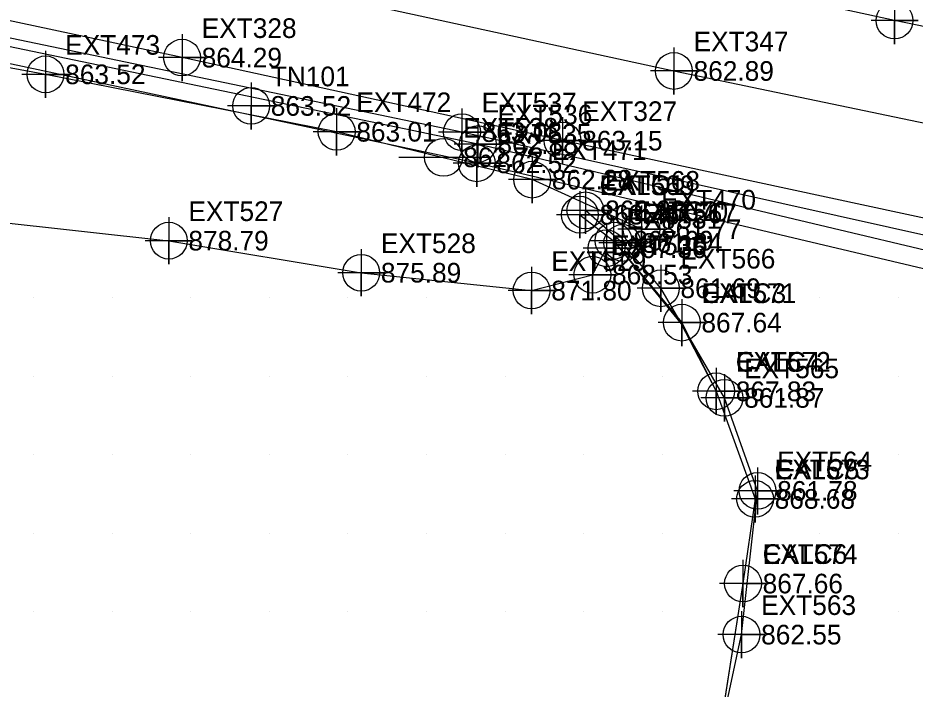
# Model space of a CAD drawing. Extents: x 1762120 to 1766775, y 709485 to 712965.
# Drawn here: x 1762528 to 1762642.2, y 712600.2 to 712685.6 of the extents above; entities that cross this region are included whole.
import ezdxf

# ---------------------------------------------------------------- set-up
doc = ezdxf.new("R2010")
doc.units = 0
for name, color, linetype in [('Default Symbol CELL', 7, 'Continuous'), ('Default Symbol Cogo Elevation', 7, 'Continuous'), ('Default Symbol Cogo Number', 7, 'Continuous'), ('Exist Building', 7, 'Continuous'), ('Exist Building Cogo Elevation', 7, 'Continuous'), ('Exist Building Cogo Number', 7, 'Continuous'), ('Exist Building Cogo Point CELL', 7, 'Continuous'), ('Exist DTM Breakline', 7, 'Continuous'), ('Exist DTM Breakline Cogo Elevation', 7, 'Continuous'), ('Exist DTM Breakline Cogo Number', 7, 'Continuous'), ('Exist DTM Breakline Cogo Point CELL', 7, 'Continuous'), ('Exist DTM Crownline', 7, 'Continuous'), ('Exist DTM Crownline Cogo Elevation', 7, 'Continuous'), ('Exist DTM Crownline Cogo Number', 7, 'Continuous'), ('Exist DTM Crownline Cogo Point CELL', 7, 'Continuous'), ('Exist DTM Drainline', 7, 'Continuous'), ('Exist DTM Drainline Cogo Elevation', 7, 'Continuous'), ('Exist DTM Drainline Cogo Number', 7, 'Continuous'), ('Exist DTM Drainline Cogo Point CELL', 7, 'Continuous'), ('Exist DTM QL2 LIDAR Elevation Point', 7, 'Continuous'), ('Exist Roads EOP', 7, 'Continuous'), ('Exist Roads EOP Cogo Elevation', 7, 'Continuous'), ('Exist Roads EOP Cogo Number', 7, 'Continuous'), ('Exist Roads EOP Cogo Point CELL', 7, 'Continuous'), ('Exist Utilities Telephone Pole CELL', 7, 'Continuous'), ('Exist Utilities Telephone Pole Cogo Elevation', 7, 'Continuous'), ('Exist Utilities Telephone Pole Cogo Number', 7, 'Continuous'), ('Exist Utilities Telephone UG FO SUE LOS C', 7, 'Continuous'), ('Exist Utilities Telephone UG FO SUE LOS C Cogo Elevation', 7, 'Continuous'), ('Exist Utilities Telephone UG FO SUE LOS C Cogo Number', 7, 'Continuous'), ('Exist Utilities Telephone UG FO SUE LOS C Cogo Point CELL', 7, 'Continuous'), ('Exist Utilities Water UG Line SUE LOS C', 7, 'Continuous'), ('Exist Utilities Water UG Line SUE LOS C Cogo Elevation', 7, 'Continuous'), ('Exist Utilities Water UG Line SUE LOS C Cogo Number', 7, 'Continuous'), ('Exist Utilities Water UG Line SUE LOS C Cogo Point CELL', 7, 'Continuous')]:
    doc.layers.add(name, color=color, linetype=linetype)

msp = doc.modelspace()

# ---------------------------------------------------------------- linework, layer by layer
at = {"layer": 'Default Symbol CELL'}
msp.add_lwpolyline([(1762557.68, 712677.39), (1762557.68, 712671.39), (1762557.68, 712674.39), (1762560.68, 712674.39), (1762554.68, 712674.39)], dxfattribs=at)
msp.add_circle((1762557.68, 712674.39), 2.34, dxfattribs=at)
at = {"layer": 'Exist Building'}
msp.add_lwpolyline([(1762599.52, 712660.55), (1762603.8, 712657.24), (1762612.48, 712646.81), (1762616.85, 712638.07), (1762621.8, 712624.37), (1762620.27, 712613.6), (1762616.96, 712592.54)], dxfattribs=at)
at = {"layer": 'Exist Building Cogo Point CELL'}
for points in [[(1762599.52, 712663.55), (1762599.52, 712657.55), (1762599.52, 712660.55), (1762602.52, 712660.55), (1762596.52, 712660.55)], [(1762603.8, 712660.24), (1762603.8, 712654.24), (1762603.8, 712657.24), (1762606.8, 712657.24), (1762600.8, 712657.24)], [(1762612.48, 712649.81), (1762612.48, 712643.81), (1762612.48, 712646.81), (1762615.48, 712646.81), (1762609.48, 712646.81)], [(1762616.85, 712641.07), (1762616.85, 712635.07), (1762616.85, 712638.07), (1762619.85, 712638.07), (1762613.85, 712638.07)], [(1762621.8, 712627.37), (1762621.8, 712621.37), (1762621.8, 712624.37), (1762624.8, 712624.37), (1762618.8, 712624.37)], [(1762620.27, 712616.6), (1762620.27, 712610.6), (1762620.27, 712613.6), (1762623.27, 712613.6), (1762617.27, 712613.6)]]:
    msp.add_lwpolyline(points, dxfattribs=at)
for centre in [(1762599.52, 712660.55), (1762603.8, 712657.24), (1762612.48, 712646.81), (1762616.85, 712638.07), (1762621.8, 712624.37), (1762620.27, 712613.6)]:
    msp.add_circle(centre, 2.34, dxfattribs=at)
at = {"layer": 'Exist DTM Breakline'}
for points in [[(1762183.31, 712740.13), (1762222.89, 712732.5), (1762242.72, 712728.2), (1762260.87, 712722.96), (1762294.89, 712713.63), (1762324.74, 712704.89), (1762362.52, 712694.51), (1762387.62, 712687.36), (1762406.26, 712681.83), (1762438.55, 712677.19), (1762458.9, 712672.51), (1762474.39, 712669.93), (1762496.2, 712663.55), (1762513.05, 712661.01), (1762547.19, 712657.24), (1762571.69, 712653.16), (1762593.37, 712650.89), (1762601.1, 712652.91), (1762602.91, 712656.27)], [(1762599.52, 712660.55), (1762603.8, 712657.24), (1762612.39, 712646.67), (1762616.85, 712638.07), (1762621.8, 712624.37), (1762620.27, 712613.6), (1762616.98, 712592.72)], [(1762615.11, 712583.99), (1762620.08, 712607.1), (1762622.12, 712625.39), (1762617.91, 712637.23), (1762609.81, 712651.18), (1762604.91, 712656.95), (1762600.21, 712661.1)]]:
    msp.add_lwpolyline(points, dxfattribs=at)
at = {"layer": 'Exist DTM Breakline Cogo Point CELL'}
for points in [[(1762600.21, 712664.1), (1762600.21, 712658.1), (1762600.21, 712661.1), (1762603.21, 712661.1), (1762597.21, 712661.1)], [(1762599.52, 712663.55), (1762599.52, 712657.55), (1762599.52, 712660.55), (1762602.52, 712660.55), (1762596.52, 712660.55)], [(1762547.19, 712660.24), (1762547.19, 712654.24), (1762547.19, 712657.24), (1762550.19, 712657.24), (1762544.19, 712657.24)], [(1762603.8, 712660.24), (1762603.8, 712654.24), (1762603.8, 712657.24), (1762606.8, 712657.24), (1762600.8, 712657.24)], [(1762602.91, 712659.27), (1762602.91, 712653.27), (1762602.91, 712656.27), (1762605.91, 712656.27), (1762599.91, 712656.27)], [(1762604.91, 712659.95), (1762604.91, 712653.95), (1762604.91, 712656.95), (1762607.91, 712656.95), (1762601.91, 712656.95)], [(1762571.69, 712656.16), (1762571.69, 712650.16), (1762571.69, 712653.16), (1762574.69, 712653.16), (1762568.69, 712653.16)], [(1762601.1, 712655.91), (1762601.1, 712649.91), (1762601.1, 712652.91), (1762604.1, 712652.91), (1762598.1, 712652.91)], [(1762593.37, 712653.89), (1762593.37, 712647.89), (1762593.37, 712650.89), (1762596.37, 712650.89), (1762590.37, 712650.89)], [(1762609.81, 712654.18), (1762609.81, 712648.18), (1762609.81, 712651.18), (1762612.81, 712651.18), (1762606.81, 712651.18)], [(1762612.48, 712649.81), (1762612.48, 712643.81), (1762612.48, 712646.81), (1762615.48, 712646.81), (1762609.48, 712646.81)], [(1762616.85, 712641.07), (1762616.85, 712635.07), (1762616.85, 712638.07), (1762619.85, 712638.07), (1762613.85, 712638.07)], [(1762617.91, 712640.23), (1762617.91, 712634.23), (1762617.91, 712637.23), (1762620.91, 712637.23), (1762614.91, 712637.23)], [(1762622.12, 712628.39), (1762622.12, 712622.39), (1762622.12, 712625.39), (1762625.12, 712625.39), (1762619.12, 712625.39)], [(1762621.8, 712627.37), (1762621.8, 712621.37), (1762621.8, 712624.37), (1762624.8, 712624.37), (1762618.8, 712624.37)], [(1762620.27, 712616.6), (1762620.27, 712610.6), (1762620.27, 712613.6), (1762623.27, 712613.6), (1762617.27, 712613.6)], [(1762620.08, 712610.1), (1762620.08, 712604.1), (1762620.08, 712607.1), (1762623.08, 712607.1), (1762617.08, 712607.1)]]:
    msp.add_lwpolyline(points, dxfattribs=at)
for centre in [(1762599.52, 712660.55), (1762600.21, 712661.1), (1762547.19, 712657.24), (1762603.8, 712657.24), (1762604.91, 712656.95), (1762602.91, 712656.27), (1762571.69, 712653.16), (1762601.1, 712652.91), (1762609.81, 712651.18), (1762593.37, 712650.89), (1762612.48, 712646.81), (1762616.85, 712638.07), (1762617.91, 712637.23), (1762622.12, 712625.39), (1762621.8, 712624.37), (1762620.27, 712613.6), (1762620.08, 712607.1)]:
    msp.add_circle(centre, 2.34, dxfattribs=at)
at = {"layer": 'Exist DTM Crownline'}
msp.add_lwpolyline([(1762166.55, 712774.69), (1762217.29, 712763.93), (1762266.93, 712753.16), (1762315.99, 712742.65), (1762361.3, 712733.13), (1762409.52, 712722.71), (1762461.51, 712711.51), (1762512.12, 712700.31), (1762561, 712689.86), (1762611.48, 712678.84), (1762663.77, 712667.96), (1762715.27, 712656.97), (1762767.73, 712645.75), (1762820.16, 712634.42), (1762873.56, 712623.12), (1762907.32, 712615.87), (1762954.84, 712607.61), (1762970.66, 712604.72)], dxfattribs=at)
at = {"layer": 'Exist DTM Crownline Cogo Point CELL'}
msp.add_lwpolyline([(1762611.48, 712681.84), (1762611.48, 712675.84), (1762611.48, 712678.84), (1762614.48, 712678.84), (1762608.48, 712678.84)], dxfattribs=at)
msp.add_circle((1762611.48, 712678.84), 2.34, dxfattribs=at)
at = {"layer": 'Exist DTM Drainline'}
msp.add_lwpolyline([(1762607.34, 712658.7), (1762593.44, 712665.01), (1762568.56, 712671.1), (1762531.51, 712678.41), (1762506.12, 712683.06), (1762483.93, 712688.33), (1762453.21, 712695.91), (1762419.5, 712702.24), (1762383.47, 712709.67), (1762355.69, 712715.12), (1762331.82, 712720.47), (1762302.4, 712727.8), (1762276.98, 712733.51), (1762241.78, 712739.93), (1762203.56, 712744.94), (1762183.53, 712748.07)], dxfattribs=at)
at = {"layer": 'Exist DTM Drainline Cogo Point CELL'}
for points in [[(1762531.51, 712681.41), (1762531.51, 712675.41), (1762531.51, 712678.41), (1762534.51, 712678.41), (1762528.51, 712678.41)], [(1762568.56, 712674.1), (1762568.56, 712668.1), (1762568.56, 712671.1), (1762571.56, 712671.1), (1762565.56, 712671.1)], [(1762593.44, 712668.01), (1762593.44, 712662.01), (1762593.44, 712665.01), (1762596.44, 712665.01), (1762590.44, 712665.01)], [(1762607.34, 712661.7), (1762607.34, 712655.7), (1762607.34, 712658.7), (1762610.34, 712658.7), (1762604.34, 712658.7)]]:
    msp.add_lwpolyline(points, dxfattribs=at)
for centre in [(1762531.51, 712678.41), (1762568.56, 712671.1), (1762593.44, 712665.01), (1762607.34, 712658.7)]:
    msp.add_circle(centre, 2.34, dxfattribs=at)
at = {"layer": 'Exist DTM QL2 LIDAR Elevation Point'}
for p, q in [((1762620, 712660), (1762620, 712660)), ((1762530, 712650), (1762530, 712650)), ((1762540, 712650), (1762540, 712650)), ((1762550, 712650), (1762550, 712650)), ((1762560, 712650), (1762560, 712650)), ((1762570, 712650), (1762570, 712650)), ((1762580, 712650), (1762580, 712650)), ((1762620, 712650), (1762620, 712650)), ((1762630, 712650), (1762630, 712650)), ((1762640, 712650), (1762640, 712650)), ((1762530, 712640), (1762530, 712640)), ((1762540, 712640), (1762540, 712640)), ((1762550, 712640), (1762550, 712640)), ((1762560, 712640), (1762560, 712640)), ((1762570, 712640), (1762570, 712640)), ((1762580, 712640), (1762580, 712640)), ((1762590, 712640), (1762590, 712640)), ((1762600, 712640), (1762600, 712640)), ((1762610, 712640), (1762610, 712640)), ((1762620, 712640), (1762620, 712640)), ((1762630, 712640), (1762630, 712640)), ((1762640, 712640), (1762640, 712640)), ((1762530, 712630), (1762530, 712630)), ((1762540, 712630), (1762540, 712630)), ((1762550, 712630), (1762550, 712630)), ((1762560, 712630), (1762560, 712630)), ((1762570, 712630), (1762570, 712630)), ((1762580, 712630), (1762580, 712630)), ((1762590, 712630), (1762590, 712630)), ((1762600, 712630), (1762600, 712630)), ((1762610, 712630), (1762610, 712630)), ((1762630, 712630), (1762630, 712630)), ((1762640, 712630), (1762640, 712630)), ((1762530, 712620), (1762530, 712620)), ((1762540, 712620), (1762540, 712620)), ((1762550, 712620), (1762550, 712620)), ((1762560, 712620), (1762560, 712620)), ((1762570, 712620), (1762570, 712620)), ((1762580, 712620), (1762580, 712620)), ((1762590, 712620), (1762590, 712620)), ((1762600, 712620), (1762600, 712620)), ((1762610, 712620), (1762610, 712620)), ((1762630, 712620), (1762630, 712620)), ((1762640, 712620), (1762640, 712620)), ((1762530, 712610), (1762530, 712610)), ((1762540, 712610), (1762540, 712610)), ((1762550, 712610), (1762550, 712610)), ((1762560, 712610), (1762560, 712610)), ((1762570, 712610), (1762570, 712610)), ((1762580, 712610), (1762580, 712610)), ((1762590, 712610), (1762590, 712610)), ((1762600, 712610), (1762600, 712610)), ((1762610, 712610), (1762610, 712610)), ((1762630, 712610), (1762630, 712610)), ((1762640, 712610), (1762640, 712610))]:
    msp.add_line(p, q, dxfattribs=at)
at = {"layer": 'Exist Roads EOP'}
for points in [[(1762972.64, 712616.33), (1762930.48, 712622.91), (1762881.99, 712633.2), (1762831.97, 712644.06), (1762782.82, 712654.41), (1762735.74, 712664.41), (1762686.68, 712675.53), (1762639.56, 712685.26), (1762589.4, 712696.15), (1762546.23, 712705.49), (1762496.4, 712716.08), (1762446.15, 712726.9), (1762396.23, 712737.69), (1762346.43, 712748.23), (1762295.97, 712759.18), (1762245.1, 712770.1), (1762193.68, 712780.97), (1762169, 712786.42)], [(1762974.58, 712585.31), (1762927.98, 712597.84), (1762890.67, 712606.3), (1762842.51, 712617.09), (1762793.23, 712628.15), (1762744.7, 712638.79), (1762696.33, 712649.07), (1762645.67, 712659.58), (1762597.31, 712669.97), (1762548.88, 712680.54), (1762499.87, 712691.04), (1762451.78, 712701.31), (1762402.08, 712712.16), (1762353.64, 712722.59), (1762304.8, 712733.11), (1762255.13, 712743.65), (1762207.34, 712753.91), (1762164.28, 712763.06), (1762150.69, 712765.78)]]:
    msp.add_lwpolyline(points, dxfattribs=at)
at = {"layer": 'Exist Roads EOP Cogo Point CELL'}
for points in [[(1762639.56, 712688.26), (1762639.56, 712682.26), (1762639.56, 712685.26), (1762642.56, 712685.26), (1762636.56, 712685.26)], [(1762548.88, 712683.54), (1762548.88, 712677.54), (1762548.88, 712680.54), (1762551.88, 712680.54), (1762545.88, 712680.54)], [(1762597.31, 712672.97), (1762597.31, 712666.97), (1762597.31, 712669.97), (1762600.31, 712669.97), (1762594.31, 712669.97)]]:
    msp.add_lwpolyline(points, dxfattribs=at)
for centre in [(1762639.56, 712685.26), (1762548.88, 712680.54), (1762597.31, 712669.97)]:
    msp.add_circle(centre, 2.34, dxfattribs=at)
at = {"layer": 'Exist Utilities Telephone Pole CELL'}
for p, q in [((1762576.49, 712667.85), (1762587.82, 712667.85)), ((1762582.16, 712667.85), (1762582.16, 712667.85))]:
    msp.add_line(p, q, dxfattribs=at)
msp.add_circle((1762582.16, 712667.85), 2.41, dxfattribs=at)
at = {"layer": 'Exist Utilities Telephone UG FO SUE LOS C'}
for points in [[(1762655.15, 712653.25), (1762586.52, 712669.54), (1762459.67, 712695.94), (1762295.49, 712731.66), (1762171.26, 712757.55)], [(1762655.08, 712650.85), (1762586.39, 712667.09), (1762459.96, 712694.03), (1762295.89, 712729.25), (1762171.95, 712754.92)]]:
    msp.add_lwpolyline(points, dxfattribs=at)
at = {"layer": 'Exist Utilities Telephone UG FO SUE LOS C Cogo Point CELL'}
for points in [[(1762586.52, 712672.54), (1762586.52, 712666.54), (1762586.52, 712669.54), (1762589.52, 712669.54), (1762583.52, 712669.54)], [(1762586.39, 712670.09), (1762586.39, 712664.09), (1762586.39, 712667.09), (1762589.39, 712667.09), (1762583.39, 712667.09)]]:
    msp.add_lwpolyline(points, dxfattribs=at)
for centre in [(1762586.52, 712669.54), (1762586.39, 712667.09)]:
    msp.add_circle(centre, 2.34, dxfattribs=at)
at = {"layer": 'Exist Utilities Water UG Line SUE LOS C'}
msp.add_lwpolyline([(1762652.6, 712655.88), (1762584.51, 712671.06), (1762460.33, 712696.95), (1762295.33, 712732.74), (1762171.02, 712758.92)], dxfattribs=at)
at = {"layer": 'Exist Utilities Water UG Line SUE LOS C Cogo Point CELL'}
msp.add_lwpolyline([(1762584.51, 712674.06), (1762584.51, 712668.06), (1762584.51, 712671.06), (1762587.51, 712671.06), (1762581.51, 712671.06)], dxfattribs=at)
msp.add_circle((1762584.51, 712671.06), 2.34, dxfattribs=at)

# ---------------------------------------------------------------- texts
at = {"layer": 'Default Symbol Cogo Elevation'}
msp.add_text('863.52', height=2.5, dxfattribs=at).set_placement((1762560.18, 712673.14))
at = {"layer": 'Default Symbol Cogo Number'}
msp.add_text('TN101', height=2.5, dxfattribs=at).set_placement((1762560.18, 712676.89))
at = {"layer": 'Exist Building Cogo Elevation'}
for s, p in [('863.45', (1762602.02, 712659.3)), ('867.69', (1762606.3, 712655.99)), ('867.64', (1762614.98, 712645.56)), ('867.83', (1762619.35, 712636.82)), ('868.68', (1762624.3, 712623.12)), ('867.66', (1762622.77, 712612.35))]:
    msp.add_text(s, height=2.5, dxfattribs=at).set_placement(p)
at = {"layer": 'Exist Building Cogo Number'}
for s, p in [('CALC1', (1762602.02, 712663.05)), ('CALC2', (1762606.3, 712659.74)), ('CALC3', (1762614.98, 712649.31)), ('CALC4', (1762619.35, 712640.57)), ('CALC5', (1762624.3, 712626.87)), ('CALC6', (1762622.77, 712616.1))]:
    msp.add_text(s, height=2.5, dxfattribs=at).set_placement(p)
at = {"layer": 'Exist DTM Breakline Cogo Elevation'}
for s, p in [('863.45', (1762602.02, 712659.3)), ('862.28', (1762602.71, 712659.85)), ('878.79', (1762549.69, 712655.99)), ('867.69', (1762606.3, 712655.99)), ('861.84', (1762607.41, 712655.7)), ('867.36', (1762605.41, 712655.02)), ('875.89', (1762574.19, 712651.91)), ('868.53', (1762603.6, 712651.67)), ('871.80', (1762595.87, 712649.64)), ('861.69', (1762612.31, 712649.94)), ('867.64', (1762614.98, 712645.56)), ('867.83', (1762619.35, 712636.82)), ('861.87', (1762620.41, 712635.98)), ('861.78', (1762624.62, 712624.14)), ('868.68', (1762624.3, 712623.12)), ('867.66', (1762622.77, 712612.35)), ('862.55', (1762622.58, 712605.85))]:
    msp.add_text(s, height=2.5, dxfattribs=at).set_placement(p)
at = {"layer": 'Exist DTM Breakline Cogo Number'}
for s, p in [('EXT568', (1762602.71, 712663.6)), ('EXT569', (1762602.02, 712663.05)), ('EXT527', (1762549.69, 712659.74)), ('EXT531', (1762605.41, 712658.77)), ('EXT570', (1762606.3, 712659.74)), ('EXT567', (1762607.41, 712659.45)), ('EXT528', (1762574.19, 712655.66)), ('EXT530', (1762603.6, 712655.42)), ('EXT529', (1762595.87, 712653.39)), ('EXT566', (1762612.31, 712653.69)), ('EXT571', (1762614.98, 712649.31)), ('EXT572', (1762619.35, 712640.57)), ('EXT565', (1762620.41, 712639.73)), ('EXT573', (1762624.3, 712626.87)), ('EXT564', (1762624.62, 712627.89)), ('EXT574', (1762622.77, 712616.1)), ('EXT563', (1762622.58, 712609.6))]:
    msp.add_text(s, height=2.5, dxfattribs=at).set_placement(p)
at = {"layer": 'Exist DTM Crownline Cogo Elevation'}
msp.add_text('862.89', height=2.5, dxfattribs=at).set_placement((1762613.98, 712677.59))
at = {"layer": 'Exist DTM Crownline Cogo Number'}
msp.add_text('EXT347', height=2.5, dxfattribs=at).set_placement((1762613.98, 712681.34))
at = {"layer": 'Exist DTM Drainline Cogo Elevation'}
for s, p in [('863.52', (1762534.01, 712677.16)), ('863.01', (1762571.06, 712669.85)), ('862.28', (1762595.94, 712663.76)), ('861.77', (1762609.84, 712657.45))]:
    msp.add_text(s, height=2.5, dxfattribs=at).set_placement(p)
at = {"layer": 'Exist DTM Drainline Cogo Number'}
for s, p in [('EXT473', (1762534.01, 712680.91)), ('EXT472', (1762571.06, 712673.6)), ('EXT471', (1762595.94, 712667.51)), ('EXT470', (1762609.84, 712661.2))]:
    msp.add_text(s, height=2.5, dxfattribs=at).set_placement(p)
at = {"layer": 'Exist Roads EOP Cogo Elevation'}
for s, p in [('864.29', (1762551.38, 712679.29)), ('863.15', (1762599.81, 712668.72))]:
    msp.add_text(s, height=2.5, dxfattribs=at).set_placement(p)
at = {"layer": 'Exist Roads EOP Cogo Number'}
for s, p in [('EXT328', (1762551.38, 712683.04)), ('EXT327', (1762599.81, 712672.47))]:
    msp.add_text(s, height=2.5, dxfattribs=at).set_placement(p)
at = {"layer": 'Exist Utilities Telephone Pole Cogo Elevation'}
msp.add_text('862.72', height=2.5, dxfattribs=at).set_placement((1762584.66, 712666.6))
at = {"layer": 'Exist Utilities Telephone Pole Cogo Number'}
msp.add_text('EXT538', height=2.5, dxfattribs=at).set_placement((1762584.66, 712670.35))
at = {"layer": 'Exist Utilities Telephone UG FO SUE LOS C Cogo Elevation'}
for s, p in [('862.88', (1762589.02, 712668.29)), ('862.52', (1762588.89, 712665.84))]:
    msp.add_text(s, height=2.5, dxfattribs=at).set_placement(p)
at = {"layer": 'Exist Utilities Telephone UG FO SUE LOS C Cogo Number'}
for s, p in [('EXT536', (1762589.02, 712672.04)), ('EXT535', (1762588.89, 712669.59))]:
    msp.add_text(s, height=2.5, dxfattribs=at).set_placement(p)
at = {"layer": 'Exist Utilities Water UG Line SUE LOS C Cogo Elevation'}
msp.add_text('863.08', height=2.5, dxfattribs=at).set_placement((1762587.01, 712669.81))
at = {"layer": 'Exist Utilities Water UG Line SUE LOS C Cogo Number'}
msp.add_text('EXT537', height=2.5, dxfattribs=at).set_placement((1762587.01, 712673.56))

doc.saveas('drawing.dxf')
